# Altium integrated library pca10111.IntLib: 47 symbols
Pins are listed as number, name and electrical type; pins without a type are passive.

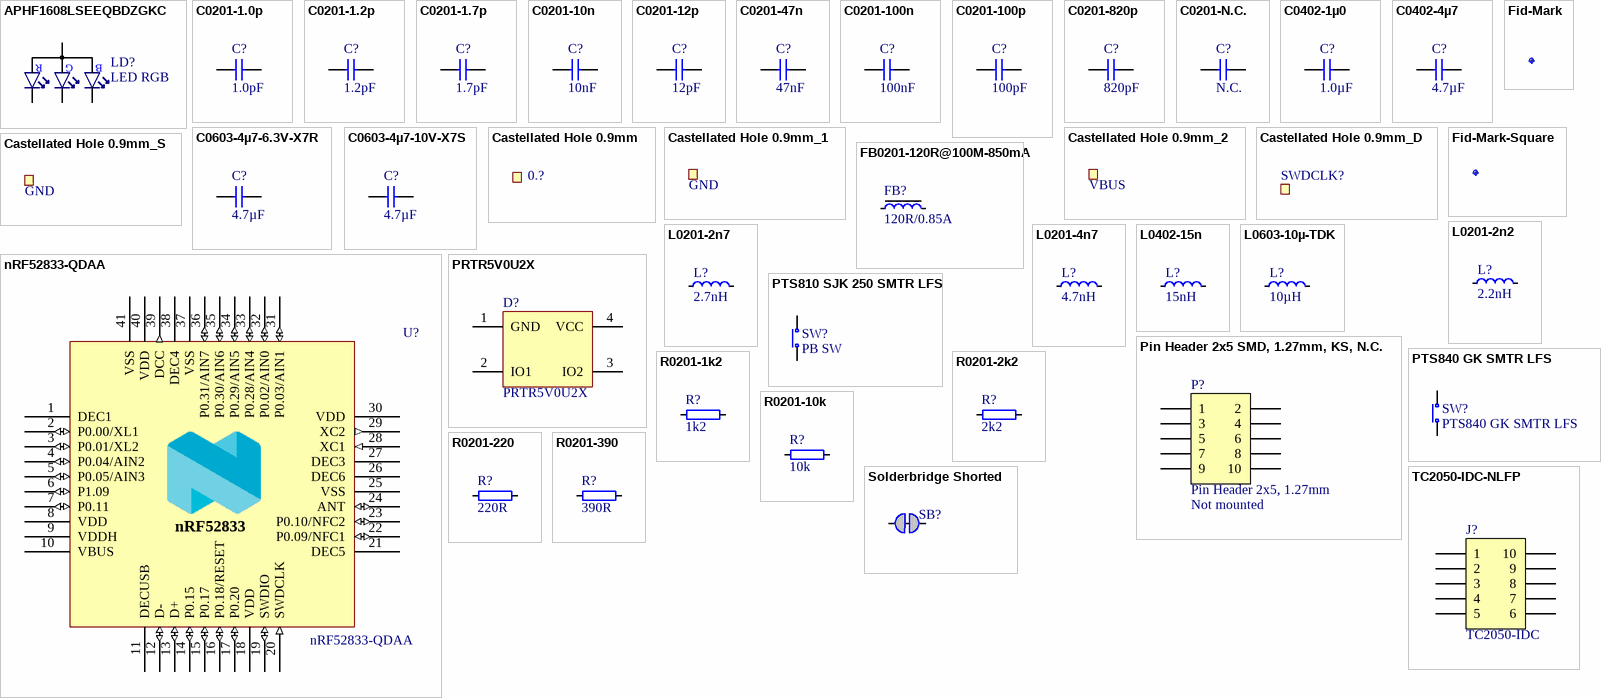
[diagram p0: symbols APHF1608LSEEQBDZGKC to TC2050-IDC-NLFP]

## APHF1608LSEEQBDZGKC
designator LD?, comment LED RGB
RGB LED 1.60 mm x 0.80 mm SMD; Part Number: APHF1608LSEEQBDZGKC; Manufacturer: Kingbright Company LLC; Part number IPS: 00000001254; Artikkelnr Noca: N.A.
footprint LED_RGB_0603
pins: 1 C_RED, 2 C_GREEN, 3 C_BLUE, 4 A

## C0201-1.0p
designator C?, comment 1.0pF
Capacitor, NP0, ±0.05pF; Part Number: C0201-1.0p
footprint CAPC0603X03L_C
pins: 1, 2

## C0201-1.2p
designator C?, comment 1.2pF
Capacitor, NP0, ±0.05pF; Part Number: C0201-1.2p
footprint CAPC0603X03L_C
pins: 1, 2

## C0201-1.7p
designator C?, comment 1.7pF
Chip Cap 0201; Part Number: C0201-1.7p; Note: Chip Cap 1%; Artikkelnr Noca: N.A.
footprint CAPC0603X03L_C
pins: 1, 2

## C0201-10n
designator C?, comment 10nF
Capacitor, X7R, ±10%; Part Number: C0201-10n; Part number IPS: 00000003480; Note: 10V; Artikkelnr Noca: N.A.
footprint CAPC0603X03L_C
pins: 1, 2

## C0201-12p
designator C?, comment 12pF
Capacitor, NP0, ±2%; Part Number: C0201-12p
footprint CAPC0603X03L_C
pins: 1, 2

## C0201-47n
designator C?, comment 47nF
Capacitor, X5R, ±10%; Part Number: C0201-47n
footprint CAPC0603X03L_C
pins: 1, 2

## C0201-100n
designator C?, comment 100nF
Capacitor, X5R, ±10%; Part Number: C0201-100n; Part number IPS: 00000001248; Note: 16V; Artikkelnr Noca: N.A.
footprint CAPC0603X03L_C
pins: 1, 2

## C0201-100p
designator C?, comment 100pF
Capacitor, NP0, ±2%; Part Number: C0201-100p
footprint CAPC0603X03L_C
pins: 1, 2

## C0201-820p
designator C?, comment 820pF
Capacitor, X7R, ±10%; Part Number: C0201-820p
footprint CAPC0603X03L_C
pins: 1, 2

## C0201-N.C.
designator C?, comment N.C.
Not mounted; Part Number: C0201-N.C.; Note: Chip Cap; Artikkelnr Noca: N.A.; Assembly: Not mounted
footprint CAPC0603X03L_C_NC
pins: 1, 2

## C0402-1µ0
designator C?, comment 1.0µF
Capacitor, X5R, ±5%; Part Number: C0402-1µ0
footprint CAPC1005X04L
pins: 1, 2

## C0402-4µ7
designator C?, comment 4.7µF
Capacitor, X5R, ±20%; Part Number: C0402-4µ7; Part number IPS: 00000001251; Note: 10V; Artikkelnr Noca: 20039482
footprint CAPC1005X04L
pins: 1, 2

## C0603-4µ7-6.3V-X7R
designator C?, comment 4.7µF
Capacitor, X7R, ±10%; Part Number: C0603-4µ7-6.3V-X7R
footprint CAPC1608X06L
pins: 1, 2

## C0603-4µ7-10V-X7S
designator C?, comment 4.7µF
Capacitor, X7S, ±10%; Part Number: C0603-4µ7-10V-X7S
footprint CAPC1608X06L
pins: 1, 2

## Castellated Hole 0.9mm
designator 0.?, comment CH  (value not drawn)  (no BOM)
Castellated Hole 0.9mm; Artikkelnr Noca: N.A.
footprint Castellated_Hole_0.9mm
pins: 1

## Castellated Hole 0.9mm_1
designator GND?, comment GND  (no BOM)
Castellated Hole 0.9mm; Artikkelnr Noca: N.A.
footprint Castellated_Hole_0.9mm
pins: 1

## Castellated Hole 0.9mm_2
designator VBUS?, comment VBUS  (no BOM)
Castellated Hole 0.9mm; Artikkelnr Noca: N.A.
footprint Castellated_Hole_0.9mm
pins: 1

## Castellated Hole 0.9mm_D
designator SWDCLK?, comment CH  (value not drawn)  (no BOM)
Castellated Hole 0.9mm; Part Number: Castellated Hole 0.9mm_D; Artikkelnr Noca: N.A.
footprint Castellated_Hole_0.9mm_D
pins: 1

## Castellated Hole 0.9mm_S
designator GND?, comment GND  (no BOM)
Castellated Hole 0.9mm; Part Number: Castellated Hole 0.9mm_S; Artikkelnr Noca: N.A.
footprint Castellated_Hole_0.9mm_S
pins: 1

## FB0201-120R@100M-850mA
designator FB?, comment 120R/0.85A
Ferrite Bead, 120 Ohm @ 100MHz, 850mA, 150 mOhm Max; Part Number: FB0201-120R@100M-850mA; Manufacturer: Taiyo Yuden; Manufacturer Part Number: BKP0603HS121-T; Part number IPS: 00000001252; Note: Chip EMIFIL Inductor Type Chip Ferrite Bead; Artikkelnr Noca: N.A.
footprint INDC0603X03L_C
pins: 1, 2

## Fid-Mark
designator Fid?, comment Fiducial mark  (value not drawn)
Part Number: Fid-Mark; Artikkelnr Noca: N.A.
footprint Fiducial

## Fid-Mark-Square
designator Fid?, comment Fiducial mark  (value not drawn)
Part Number: Fid-Mark-Square; Artikkelnr Noca: N.A.
footprint Fiducial_Square

## L0201-2n2
designator L?, comment 2.2nH
High frequency chip inductor ±5%; Part Number: L0201-2n2
footprint INDC0603X03L_C
pins: 1, 2

## L0201-2n7
designator L?, comment 2.7nH
Chip Inductor; Part Number: L0201-2n7; Note: High frequency chip inductor ±5%; Artikkelnr Noca: N.A.
footprint INDC0603X03L_C
pins: 1, 2

## L0201-4n7
designator L?, comment 4.7nH
High frequency chip inductor ±5%; Part Number: L0201-4n7
footprint INDC0603X03L_C
pins: 1, 2

## L0402-15n
designator L?, comment 15nH
High frequency chip inductor ±10%; Part Number: L0402-15n
footprint INDC1005X04L
pins: 1, 2

## L0603-10µ-TDK
designator L?, comment 10µH
Chip inductor, IDC,min = 50 mA, ±20%; Part Number: L0603-10µ-TDK
footprint INDC1608X06L
pins: 1, 2

## nRF52833-QDAA
designator U?
Multi-protocol Bluetooth Low Energy, IEEE 802.15.4, ANT and 2.4GHz proprietary system-on-chip; Manufacturer: Nordic Semiconductor; Artikkelnr Noca: N.A.
footprint QFN40P500X500X50_HS-41N
pins: 1 DEC1 (power), 2 P0.00/XL1 (io), 3 P0.01/XL2 (io), 4 P0.04/AIN2 (io), 5 P0.05/AIN3 (io), 6 P1.09 (io), 7 P0.11 (io), 8 VDD (power), 9 VDDH (power), 10 VBUS (power), 11 DECUSB (power), 12 D- (io), 13 D+ (io), 14 P0.15 (io), 15 P0.17 (io), 16 P0.18/RESET (io), 17 P0.20 (io), 18 VDD (power), 19 SWDIO (io), 20 SWDCLK (in), 21 DEC5 (power), 22 P0.09/NFC1 (io), 23 P0.10/NFC2 (io), 24 ANT (io), 25 VSS (power), 26 DEC6 (power), 27 DEC3 (power), 28 XC1 (in), 29 XC2 (out), 30 VDD (power), 31 P0.03/AIN1 (io), 32 P0.02/AIN0 (io), 33 P0.28/AIN4 (io), 34 P0.29/AIN5 (io), 35 P0.30/AIN6 (io), 36 P0.31/AIN7 (io), 37 VSS (power), 38 DEC4 (power), 39 DCC (out), 40 VDD (power), 41 VSS (power)

## Pin Header 2x5 SMD, 1.27mm, KS, N.C.
designator P?, comment Pin Header 2x5, 1.27mm  Assembly: Not mounted
Pin Header 2x5, 1.27mm (50mil), SMD, Keying Shroud; Part Number: Pin Header 2x5 SMD, 1.27mm, KS, N.C.; Manufacturer: W-CON; Manufacturer Part Number: 3132-10MS0BK00R1; Artikkelnr Noca: N.A.
footprint HDR_2x5-SMD-1.27mm-NC
pins: 1, 2, 3, 4, 5, 6, 7, 8, 9, 10

## PRTR5V0U2X
designator D?
Ultra low capacitance double rail-to-rail ESD protection diode; Manufacturer: NXP; Part number IPS: 00000009951; Artikkelnr Noca: 10069015
footprint SOT190P230X110-4L
pins: 1 GND, 2 IO1, 3 IO2, 4 VCC

## PTS810 SJK 250 SMTR LFS
designator SW?, comment PB SW
Tactile Switch, SPNO, SMD, 260gf, 4.2x3.2x2.5mm; Part Number: PTS810 SJK 250 SMTR LFS; Manufacturer: C&K Components; Part number IPS: 00000001259; Artikkelnr Noca: N.A.
footprint C&K_PTS810
pins: 1 N.O, 2 COM

## PTS840 GK SMTR LFS
designator SW?
Microminiature SMT Switch, Side Actuated; Manufacturer: C&K Components; Part number IPS: 00000001260; Note: Tactile Switch, SPST, SMD, 220gf; Artikkelnr Noca: 50019089
footprint EVQP7A/J/B/K
pins: 1 N.O, 2 COM

## R0201-1k2
designator R?, comment 1k2
Resistor, ±1%, 0.05W; Part Number: R0201-1k2; Part number IPS: 00000001256; Note: Chip Res 1%; Artikkelnr Noca: N.A.
footprint RESC0603X03L_C
pins: 1, 2

## R0201-2k2
designator R?, comment 2k2
Resistor, ±1%, 0.05W; Part Number: R0201-2k2; Part number IPS: 00000001257; Note: Chip Res 1%; Artikkelnr Noca: N.A.
footprint RESC0603X03L_C
pins: 1, 2

## R0201-10k
designator R?, comment 10k
Resistor, ±1%, 0.05W; Part Number: R0201-10k; Part number IPS: 00000001255; Note: Chip Res 1%; Artikkelnr Noca: N.A.
footprint RESC0603X03L_C
pins: 1, 2

## R0201-220
designator R?, comment 220R
Resistor, ±1%, 0.05W; Part Number: R0201-220; Part number IPS: 00000000863; Note: Chip Res 1%; Artikkelnr Noca: N.A.
footprint RESC0603X03L_C
pins: 1, 2

## R0201-390
designator R?, comment 390R
Resistor, ±1%, 0.05W; Part Number: R0201-390; Part number IPS: 00000001258; Note: Chip Res 1%; Artikkelnr Noca: N.A.
footprint RESC0603X03L_C
pins: 1, 2

## Solderbridge Shorted
designator SB?, comment Solderbridge  (value not drawn)  (net tie, no BOM)
Shorted Solderbridge; Part Number: Solderbridge Shorted; Artikkelnr Noca: N.A.
footprint Solderbridge_Shorted
pins: 1 0, 2 1

## TC2050-IDC-NLFP
designator J?, comment TC2050-IDC  (no BOM)
CBL PLUG-OF-NAILS 10-PIN; Part Number: TC2050-IDC-NLFP; Manufacturer: Tag-Connect LLC; Artikkelnr Noca: N.A.
footprint TC2050-IDC-NLFP
pins: 1, 2, 3, 4, 5, 6, 7, 8, 9, 10

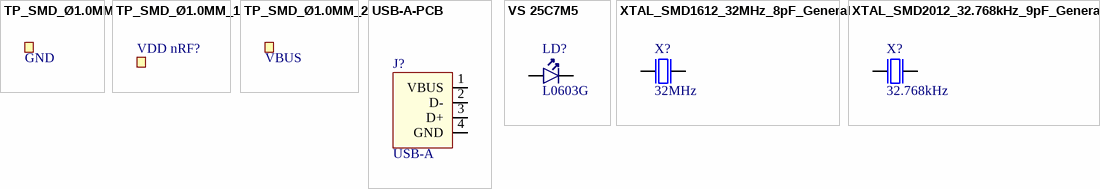
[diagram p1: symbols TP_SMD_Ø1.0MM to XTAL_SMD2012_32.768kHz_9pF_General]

## TP_SMD_Ø1.0MM
designator GND?, comment GND  (no BOM)
1.0mm circular SMD testpad; Part Number: TP_SMD_Ø1.0MM; Manufacturer: Nordic Semiconductor; Artikkelnr Noca: N.A.
footprint TP_SMD_Ø1.0mm
pins: 1

## TP_SMD_Ø1.0MM_1
designator VDD nRF?, comment Ø1.0mm,SMD  (value not drawn)  (no BOM)
1.0mm circular SMD testpad; Part Number: TP_SMD_Ø1.0MM; Manufacturer: Nordic Semiconductor; Artikkelnr Noca: N.A.
footprint TP_SMD_Ø1.0mm
pins: 1

## TP_SMD_Ø1.0MM_2
designator VBUS?, comment VBUS  (no BOM)
1.0mm circular SMD testpad; Part Number: TP_SMD_Ø1.0MM; Manufacturer: Nordic Semiconductor; Artikkelnr Noca: N.A.
footprint TP_SMD_Ø1.0mm
pins: 1

## USB-A-PCB
designator J?, comment USB-A  (no BOM)
USB-A PCB footprint; Part Number: USB-A-PCB; Artikkelnr Noca: N.A.
footprint USB-A-PCB
pins: 1 VBUS, 2 D-, 3 D+, 4 GND

## VS 25C7M5
designator LD?, comment L0603G
LED, Green, 0603, 573nm, Vf=2.0V, 24mcd, - 40 to +85°C; Part Number: VS 25C7M5; Manufacturer: Victory Electronics; Part number IPS: N.A.; Artikkelnr Noca: 13019193
footprint LED_0603_G
pins: 1 C, 2 A

## XTAL_SMD1612_32MHz_8pF_General
designator X?, comment 32MHz
XTAL SMD 1612, 32MHz, Cl=8pF, Total Tol: ±40ppm; Part Number: XTAL_SMD1612_32MHz_8pF_General
footprint BT-XTAL_1612
pins: 1 inp, 2 GND hidden to GND, 3 out, 4 GND hidden to GND

## XTAL_SMD2012_32.768kHz_9pF_General
designator X?, comment 32.768kHz
XTAL SMD 2012, 32.768kHz, Cl=9pF, Total Tol: ±50ppm; Part Number: XTAL_SMD2012_32.768kHz_9pF_General
footprint XTAL_2012
pins: 1 inp, 2 out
